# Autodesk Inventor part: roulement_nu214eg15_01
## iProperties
Shininess: 64.0
Length Units: 11269
Angle Units: 11279
Time Units: 11290
Mass Units: 11283
Length Display Precision: 3
Angle Display Precision: 2
Compacted: True
Part Number: roulement_nu214eg15_01
Document SubType Name: Modeling
Created: 2005-02
Material: Par défaut
Designer: LEGERET Philippe
Density: 0.0
Volumn: 0.0
Area: 0.0
PropertySet Name: Model Information
Control State: 0
Master: False
Checked Out: False
Author: LEGERET Philippe
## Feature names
1. Base1
